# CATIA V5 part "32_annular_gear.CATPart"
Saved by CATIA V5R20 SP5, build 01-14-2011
Part number: 32_annular_gear
Bounding box of the stored display mesh (mm): x -51.726 to 51.726, y 0 to 11.532, z -51.68 to 51.723
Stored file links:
  C:\Documents and Settings\anizard\Bureau\13\32_annular_gear.CATPart
  C:\Documents and Settings\anizard\Bureau\13\anizard.CATProduct
  C:\Documents and Settings\anizard\Bureau\13\21_casing.CATPart
  C:\Documents and Settings\anizard\Bureau\13\32_squelette.CATPart
  C:\Documents and Settings\anizard\Bureau\13\21_squelette.CATPart
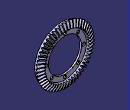
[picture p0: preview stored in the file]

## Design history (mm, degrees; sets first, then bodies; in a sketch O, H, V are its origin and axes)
External parameters (linked from other documents)
  External.module = 2 mm
  External.Z1 = 51
  External.L = 54.7814 mm
  External.nb_trou_21_32 = 8
Set1
  Plane1: linked copy from another document
  Plane2: linked copy from another document
  Line1 to Line4: linked copy from another document
  Point1: linked copy from another document
  Point2: linked copy from another document
  Sketch1, origin (0, -23.0532, -39.6607), H (-1, 0, 0), V (0, -0.931, 0.3651), geometry linked from another document
  Sketch2, origin (0, -17.942, -26.6271), H (-1, 0, 0), V (0, -0.931, 0.3651), geometry linked from another document
  DatumPoint1: linked copy from another document
  DatumPoint2: linked copy from another document
  Point3: linked copy from another document
Body1 (main body)
  Sketch3 on yz-plane, origin (0, 0, 0), H (0, 1, 0), V (0, 0, 1)
    point P1 (11.5322, -40.871)
    line L1 (11.5322, -40.871) -> (7.7247, -51.7305)
    line L2 (7.7247, -51.7305) -> (0, -48.7012)
    line L3 (0, -48.7012) -> (0, -37.5)
    line L4 (0, -37.5) -> (3.2, -37.5)
    line L5 (3.2, -37.5) -> (3.2, -30)
    line L6 (3.2, -30) -> (6.2, -30)
    line L7 (6.2, -30) -> (6.2, -38.7799)
    line L8 (6.2, -38.7799) -> (11.5322, -40.871)
    point P9 (11.5322, -40.871)
    reference intersected line E1 through (0, 0) direction (0, 1) from Plane1
    reference projected line E2 (-107.5, 37.5) -> (92.5, 37.5) from Line1
    reference projected line E3 (-107.5, 0) -> (92.5, 0) from Line2
    reference projected line E4 (-107.5, 0) -> (92.5, 0) from Line2
    reference projected line E5 (-2.5207, -80.9522) -> (25.651, -0.6018) from Line3
    reference projected line E6 (-5.4622, -79.8767) -> (25.6235, -0.6081) from Line4
    reference projected point E7 (5.8619, -51) from Point1
    reference intersected line E8 through (3, 0) direction (0, 1) from Plane2
    reference projected line E9 (-1.6783, -70.2275) -> (25.6235, -0.6081) from Line4
    reference projected point E10 (10.0605, -40.2938) from Point2
    distance L5 L7 = 3
    distance L6 E4 = 30
    distance L5 E8 = 0.2
    vertical: L3 V, L5 V, L7 V
    horizontal: L4 H, L6 H
    coincidence: L3 E1, L1 E5, L2 E7, P1 P9, L8 E10
    symmetry: E2 L4 E3
    perpendicularity: L2 E6, L8 E9
  Shaft1: profile Sketch3, axis Line2, angle 360
  Loft1: solid, Sections (Sketch1; Sketch2)
  CircPattern1: of Loft1, instances 52 {= External.Z1 + 1}, angular step 7.0588 {= 360deg/(External.Z1 )}, axis from Line2
  Sketch4 on face of Shaft1 from Sketch3.L7, origin (0, 6.2, 34), H (1, 0, 0), V (0, 0, -1)
    point P1 (0, 0)
    reference projected point E1 (0, 0) from Point3
    coincidence: E1 P1
  Hole1: placed by Sketch4, at (0, 6.2, 34) direction (0, -1, 0), diameter 4, through (limit type 6), countersink depth 1, countersink angle 90
  CircPattern2: of Hole1, instances 9 {= External.nb_trou_21_32 +1}, angular step 45, axis from Line2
